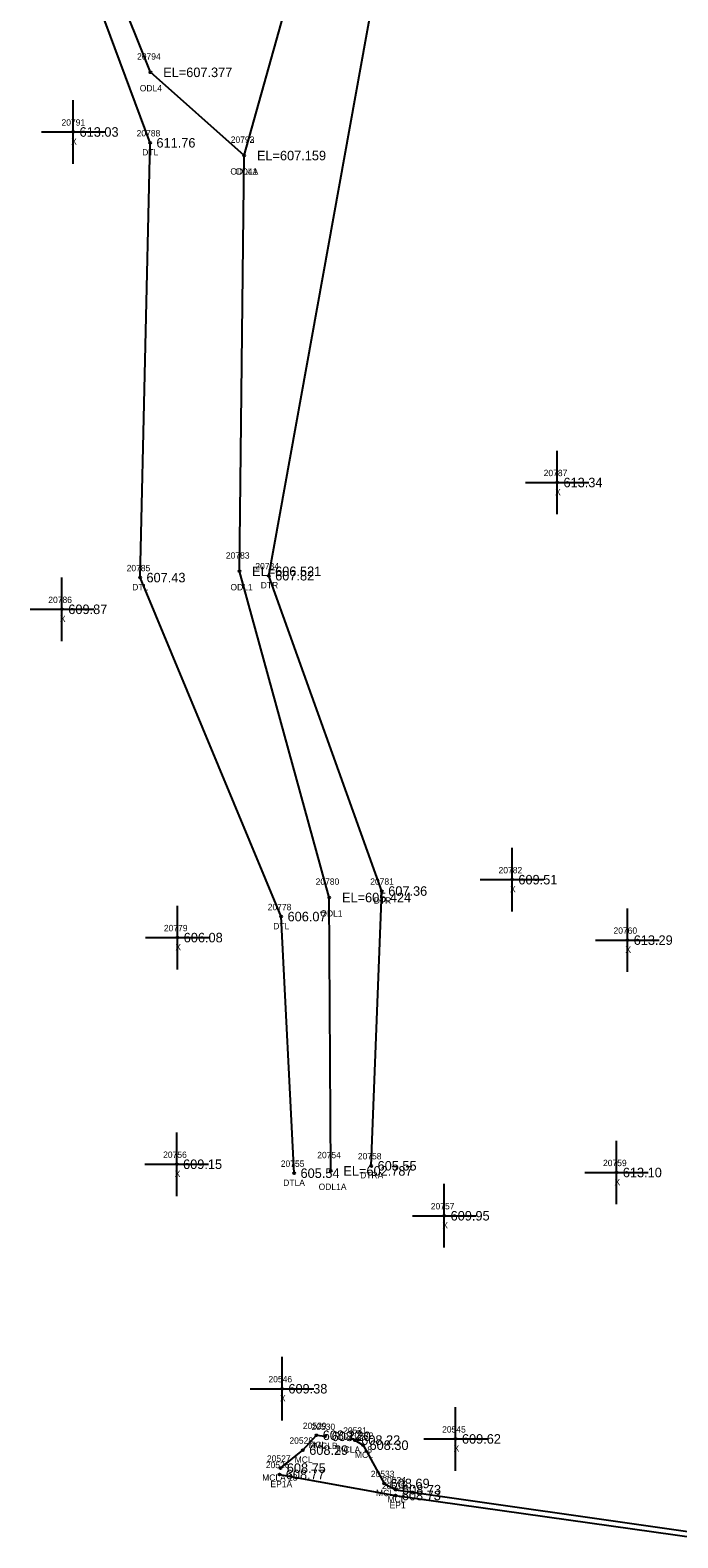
# Model space of a CAD drawing. Extents: x 1695443 to 1696344, y 1087542 to 1090645.
# Drawn here: x 1695694.7 to 1695796.6, y 1089964.5 to 1090201.9 of the extents above; entities that cross this region are included whole.
import ezdxf

# ---------------------------------------------------------------- set-up
doc = ezdxf.new("R2010")
doc.units = 0
for name, color, linetype in [('RD_EX_Conc', 7, 'Continuous'), ('RD_EX_Conc_txCode', 7, 'Continuous'), ('RD_EX_H2O', 7, 'Continuous'), ('RD_EX_H2O_txCode', 7, 'Continuous'), ('RD_EX_Misc', 7, 'Continuous'), ('RD_EX_Misc_txCode', 7, 'Continuous'), ('RD_EX_Road', 7, 'Continuous'), ('RD_EX_Road_txCode', 7, 'Continuous'), ('RD_EX_TX_Conc_ELEV', 7, 'Continuous'), ('RD_EX_TX_H2O_ELEV', 7, 'Continuous'), ('RD_EX_TX_Misc_ELEV', 7, 'Continuous'), ('RD_EX_TX_Road_ELEV', 7, 'Continuous'), ('RD_SMD_Locator', 7, 'Continuous')]:
    doc.layers.add(name, color=color, linetype=linetype)

msp = doc.modelspace()

# ---------------------------------------------------------------- linework, layer by layer
at = {"layer": 'RD_EX_Conc'}
for points in [[(1695734.1, 1089975.5), (1695737.63, 1089978.33), (1695739.75, 1089980.66), (1695741.15, 1089980.5)], [(1695745.81, 1089979.91), (1695747.12, 1089979.1), (1695750.44, 1089973.08), (1695752.24, 1089972.1), (1695799.67, 1089965.3), (1695807.74, 1089966.97), (1695812.72, 1089971.11)]]:
    msp.add_lwpolyline(points, dxfattribs=at)
at = {"layer": 'RD_EX_H2O'}
for points in [[(1695742.01, 1090022.28), (1695741.79, 1090065.32), (1695727.64, 1090116.67), (1695728.4, 1090182.12), (1695739.32, 1090221.09), (1695746.13, 1090251.36), (1695744.91, 1090257.64), (1695725.79, 1090335.12), (1695755.22, 1090445.54), (1695779.78, 1090508.81), (1695821.26, 1090580.72), (1695835.53, 1090588.18), (1695868.63, 1090584.25)], [(1695748.39, 1090023.09), (1695750.06, 1090066.34), (1695732.27, 1090115.98), (1695751.04, 1090219.89), (1695755.24, 1090253.72), (1695734.04, 1090337.88), (1695767.29, 1090450.9), (1695816.74, 1090515.62), (1695823.85, 1090555.53), (1695842.49, 1090575.31), (1695858.41, 1090574.71), (1695872.4, 1090582.09)], [(1695736.26, 1090021.92), (1695734.22, 1090062.32), (1695712.02, 1090115.68), (1695713.59, 1090184.13), (1695696.25, 1090230.9)], [(1695728.4, 1090182.12), (1695713.65, 1090195.22), (1695702.86, 1090222.28)]]:
    msp.add_lwpolyline(points, dxfattribs=at)
at = {"layer": 'RD_EX_Misc'}
for p, q in [((1695701.49, 1090180.83), (1695701.49, 1090190.83)), ((1695696.49, 1090185.83), (1695706.49, 1090185.83)), ((1695777.64, 1090125.65), (1695777.64, 1090135.65)), ((1695772.64, 1090130.65), (1695782.64, 1090130.65)), ((1695699.72, 1090105.69), (1695699.72, 1090115.69)), ((1695694.72, 1090110.69), (1695704.72, 1090110.69)), ((1695770.54, 1090063.13), (1695770.54, 1090073.13)), ((1695765.54, 1090068.13), (1695775.54, 1090068.13)), ((1695717.88, 1090054.01), (1695717.88, 1090064.01)), ((1695788.69, 1090053.61), (1695788.69, 1090063.61)), ((1695712.88, 1090059.01), (1695722.88, 1090059.01)), ((1695783.69, 1090058.61), (1695793.69, 1090058.61)), ((1695717.78, 1090018.33), (1695717.78, 1090028.33)), ((1695786.98, 1090017.03), (1695786.98, 1090027.03)), ((1695712.78, 1090023.33), (1695722.78, 1090023.33)), ((1695781.98, 1090022.03), (1695791.98, 1090022.03)), ((1695759.88, 1090010.22), (1695759.88, 1090020.22)), ((1695754.88, 1090015.22), (1695764.88, 1090015.22)), ((1695734.35, 1089982.99), (1695734.35, 1089992.99)), ((1695729.35, 1089987.99), (1695739.35, 1089987.99)), ((1695761.66, 1089975.09), (1695761.66, 1089985.09)), ((1695756.66, 1089980.09), (1695766.66, 1089980.09))]:
    msp.add_line(p, q, dxfattribs=at)
at = {"layer": 'RD_EX_Road'}
msp.add_lwpolyline([(1695733.94, 1089974.49), (1695752.2, 1089971.18), (1695799.58, 1089964.52), (1695808.15, 1089966.05), (1695812.58, 1089968.74), (1695812.72, 1089971.11), (1695815.83, 1089973.5), (1695820.51, 1089978.16)], dxfattribs=at)
at = {"layer": 'RD_SMD_Locator'}
for centre in [(1695713.65, 1090195.22), (1695701.49, 1090185.83), (1695713.59, 1090184.13), (1695728.4, 1090182.12), (1695728.4, 1090182.12), (1695777.64, 1090130.65), (1695727.64, 1090116.67), (1695712.02, 1090115.68), (1695732.27, 1090115.98), (1695699.72, 1090110.69), (1695770.54, 1090068.13), (1695741.79, 1090065.32), (1695750.06, 1090066.34), (1695734.22, 1090062.32), (1695717.88, 1090059.01), (1695788.69, 1090058.61), (1695717.78, 1090023.33), (1695736.26, 1090021.92), (1695742.01, 1090022.28), (1695748.39, 1090023.09), (1695786.98, 1090022.03), (1695759.88, 1090015.22), (1695734.35, 1089987.99), (1695739.75, 1089980.66), (1695741.15, 1089980.5), (1695745.81, 1089979.91), (1695747.12, 1089979.1), (1695761.66, 1089980.09), (1695737.63, 1089978.33), (1695733.94, 1089974.49), (1695734.1, 1089975.5), (1695750.44, 1089973.08), (1695752.24, 1089972.1), (1695752.2, 1089971.18)]:
    msp.add_circle(centre, 0.15, dxfattribs=at)

# ---------------------------------------------------------------- texts
at = {"layer": 'RD_EX_Conc_txCode'}
for s, p in [('20529', (1695737.63, 1089981.66)), ('20530', (1695738.99, 1089981.5)), ('20531', (1695743.97, 1089980.91)), ('20528', (1695735.51, 1089979.33)), ('MCL', (1695738.46, 1089978.66)), ('MCLB', (1695739.38, 1089978.5)), ('MCLA 18', (1695742.93, 1089977.91)), ('20532', (1695745, 1089980.1)), ('20527', (1695731.98, 1089976.5)), ('MCL', (1695736.34, 1089976.33)), ('MCL', (1695745.82, 1089977.1)), ('MCLA 18', (1695731.22, 1089973.5)), ('20533', (1695748.32, 1089974.08)), ('20534', (1695750.13, 1089973.1)), ('MCL', (1695749.15, 1089971.08)), ('MCL', (1695750.95, 1089970.1))]:
    msp.add_text(s, height=1, dxfattribs=at).set_placement(p)
at = {"layer": 'RD_EX_H2O_txCode'}
for s, p in [('20794', (1695711.54, 1090197.22)), ('ODL4', (1695711.96, 1090192.22)), ('20788', (1695711.47, 1090185.13)), ('DTL', (1695712.35, 1090182.13)), ('20792', (1695726.28, 1090184.12)), ('20793', (1695726.28, 1090184.12)), ('ODL4A', (1695726.22, 1090179.12)), ('ODL1', (1695726.99, 1090179.12)), ('20783', (1695725.52, 1090118.67)), ('20785', (1695709.9, 1090116.68)), ('20784', (1695730.15, 1090116.98)), ('DTL', (1695710.78, 1090113.68)), ('ODL1', (1695726.23, 1090113.67)), ('DTR', (1695731, 1090113.98)), ('20780', (1695739.64, 1090067.32)), ('20781', (1695748.23, 1090067.34)), ('20778', (1695732.1, 1090063.32)), ('DTR', (1695748.79, 1090064.34)), ('ODL1', (1695740.38, 1090062.32)), ('DTL', (1695732.97, 1090060.32)), ('20755', (1695734.15, 1090022.92)), ('20754', (1695739.89, 1090024.28)), ('20758', (1695746.28, 1090024.09)), ('DTRA', (1695746.64, 1090021.09)), ('DTLA', (1695734.53, 1090019.92)), ('ODL1A', (1695740.11, 1090019.28))]:
    msp.add_text(s, height=1, dxfattribs=at).set_placement(p)
at = {"layer": 'RD_EX_Misc_txCode'}
for s, p in [('20791', (1695699.65, 1090186.83)), ('X', (1695701.17, 1090183.83)), ('20787', (1695775.52, 1090131.65)), ('X', (1695777.32, 1090128.65)), ('20786', (1695697.57, 1090111.69)), ('X', (1695699.4, 1090108.69)), ('20782', (1695768.42, 1090069.13)), ('X', (1695770.23, 1090066.13)), ('20779', (1695715.76, 1090060.01)), ('20760', (1695786.51, 1090059.61)), ('X', (1695717.56, 1090057.01)), ('X', (1695788.38, 1090056.61)), ('20756', (1695715.64, 1090024.33)), ('20759', (1695784.86, 1090023.03)), ('X', (1695717.46, 1090021.33)), ('X', (1695786.67, 1090020.03)), ('20757', (1695757.76, 1090016.22)), ('X', (1695759.57, 1090013.22)), ('20546', (1695732.21, 1089988.99)), ('X', (1695734.03, 1089985.99)), ('20545', (1695759.54, 1089981.09)), ('X', (1695761.35, 1089978.09))]:
    msp.add_text(s, height=1, dxfattribs=at).set_placement(p)
at = {"layer": 'RD_EX_Road_txCode'}
for s, p in [('20526', (1695731.8, 1089975.49)), ('EP1A', (1695732.53, 1089972.49)), ('20535', (1695750.08, 1089972.18)), ('EP1', (1695751.28, 1089969.18))]:
    msp.add_text(s, height=1, dxfattribs=at).set_placement(p)
at = {"layer": 'RD_EX_TX_Conc_ELEV'}
for s, p in [('608.22', (1695740.75, 1089979.91)), ('608.20', (1695742.15, 1089979.75)), ('608.29', (1695738.63, 1089977.58)), ('608.22', (1695746.81, 1089979.16)), ('608.30', (1695748.12, 1089978.35)), ('608.75', (1695735.1, 1089974.75)), ('608.69', (1695751.44, 1089972.33)), ('608.73', (1695753.24, 1089971.35))]:
    msp.add_text(s, height=1.5, dxfattribs=at).set_placement(p)
at = {"layer": 'RD_EX_TX_H2O_ELEV'}
for s, p in [('EL=607.377', (1695715.65, 1090194.47)), ('611.76', (1695714.59, 1090183.38)), ('EL=607.159', (1695730.4, 1090181.37)), ('EL=607.159', (1695730.4, 1090181.37)), ('607.43', (1695713.02, 1090114.93)), ('EL=606.521', (1695729.64, 1090115.92)), ('607.82', (1695733.27, 1090115.23)), ('607.36', (1695751.06, 1090065.59)), ('EL=605.424', (1695743.79, 1090064.57)), ('606.07', (1695735.22, 1090061.57)), ('605.55', (1695749.39, 1090022.34)), ('605.54', (1695737.26, 1090021.17)), ('EL=602.787', (1695744.01, 1090021.53))]:
    msp.add_text(s, height=1.5, dxfattribs=at).set_placement(p)
at = {"layer": 'RD_EX_TX_Misc_ELEV'}
for s, p in [('613.03', (1695702.49, 1090185.08)), ('613.34', (1695778.64, 1090129.9)), ('609.87', (1695700.72, 1090109.94)), ('609.51', (1695771.54, 1090067.38)), ('606.08', (1695718.88, 1090058.26)), ('613.29', (1695789.69, 1090057.86)), ('609.15', (1695718.78, 1090022.58)), ('613.10', (1695787.98, 1090021.28)), ('609.95', (1695760.88, 1090014.47)), ('609.38', (1695735.35, 1089987.24)), ('609.62', (1695762.66, 1089979.34))]:
    msp.add_text(s, height=1.5, dxfattribs=at).set_placement(p)
at = {"layer": 'RD_EX_TX_Road_ELEV'}
for s, p in [('608.77', (1695734.94, 1089973.74)), ('608.73', (1695753.2, 1089970.43))]:
    msp.add_text(s, height=1.5, dxfattribs=at).set_placement(p)

doc.saveas('drawing.dxf')
